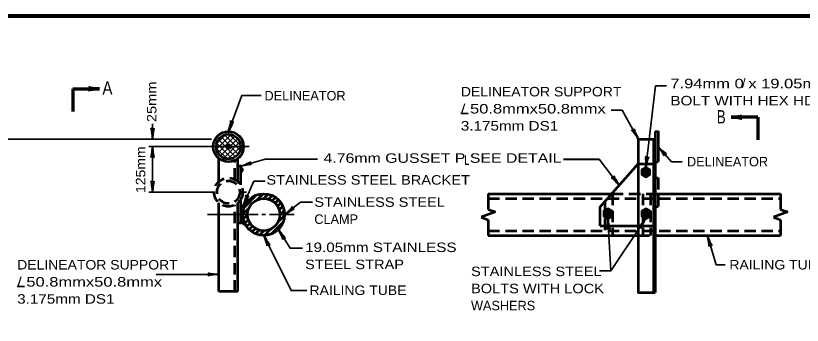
# Model space of a CAD drawing. Extents: x -105 to 751, y -65 to 479.
# Drawn here: x 59.6 to 308.2, y 374.9 to 472.7 of the extents above; entities that cross this region are included whole.
import ezdxf

# ---------------------------------------------------------------- set-up
doc = ezdxf.new("R2010")
doc.units = 0
doc.header["$LTSCALE"] = 1.2
doc.linetypes.add('MEDIUM_DASHED', pattern=[4.5, 3, -1.5])
doc.layers.add('1', color=7, linetype='Continuous', lineweight=35)

msp = doc.modelspace()

# ---------------------------------------------------------------- hatches: boundary and pattern name
at = {"layer": '1'}
msp.add_hatch(color=256, dxfattribs=at).paths.add_polyline_path([(127.405, 431.334, 1), (126.205, 431.334, 1)])

# ---------------------------------------------------------------- linework, layer by layer
at = {"layer": '1', "lineweight": 70}
for p, q in [((77.611, 449.646), (86.011, 449.646)), ((77.611, 449.646), (77.611, 442.446)), ((294.147, 440.646), (285.747, 440.646)), ((294.147, 440.646), (294.147, 433.446))]:
    msp.add_line(p, q, dxfattribs=at)
at = {"layer": '1'}
for p, q in [((200.312, 441.826), (202.577, 441.826)), ((102.805, 433.734), (102.805, 438.534)), ((130.681, 431.634), (127.105, 435.211)), ((-18.611, 433.734), (121.448, 433.734)), ((123.003, 430.516), (127.623, 435.136)), ((123.022, 432.232), (125.907, 435.117)), ((123.489, 429.305), (128.834, 434.65)), ((129.066, 428.158), (123.63, 433.594)), ((124.268, 428.387), (129.751, 433.871)), ((129.924, 428.997), (124.469, 434.452)), ((125.319, 427.741), (130.398, 432.82)), ((130.508, 430.111), (125.583, 435.036)), ((101.605, 431.334), (133.405, 431.334)), ((102.805, 416.934), (102.805, 431.334)), ((126.36, 427.47), (122.939, 430.891)), ((127.924, 427.603), (123.075, 432.452)), ((126.715, 427.44), (130.698, 431.423)), ((129.459, 428.487), (129.635, 428.663)), ((250.347, 419.101), (244.043, 427.366)), ((122.305, 416.934), (101.605, 416.934)), ((132.505, 416.934), (131.305, 416.934)), ((136.164, 409.868), (120.179, 409.868)), ((138.564, 409.868), (137.364, 409.868)), ((147.564, 409.868), (139.764, 409.868)), ((123.779, 390.962), (103.979, 390.962)), ((247.703, 392.118), (244.157, 392.118)), ((60.043, 387.126), (62.308, 387.126))]:
    msp.add_line(p, q, dxfattribs=at)
at = {"layer": '1', "lineweight": 53}
for p, q in [((261.747, 436.134), (261.747, 385.268)), ((256.347, 433.734), (261.747, 433.734)), ((261.147, 433.734), (261.147, 385.268)), ((123.779, 420.265), (123.779, 427.608)), ((129.779, 420.311), (129.779, 427.567)), ((256.347, 425.934), (261.147, 425.934)), ((261.747, 426.534), (262.647, 426.534)), ((130.679, 425.167), (129.779, 425.167)), ((130.679, 419.224), (130.679, 425.167)), ((130.679, 424.567), (130.679, 423.367)), ((257.448, 423.325), (258.817, 424.694)), ((257.448, 423.112), (258.952, 424.616)), ((257.448, 423.537), (258.507, 424.596)), ((257.448, 422.9), (259.086, 424.538)), ((257.448, 422.688), (259.22, 424.461)), ((257.448, 423.749), (258.005, 424.306)), ((257.448, 423.961), (257.503, 424.016)), ((257.453, 422.481), (258.31, 423.338)), ((257.588, 422.404), (258.311, 423.127)), ((257.722, 422.326), (258.376, 422.98)), ((257.857, 422.248), (258.48, 422.872)), ((257.991, 422.171), (258.623, 422.802)), ((258.125, 422.093), (258.824, 422.791)), ((258.26, 422.015), (260.046, 423.801)), ((258.394, 421.938), (260.046, 423.589)), ((258.529, 421.86), (260.046, 423.377)), ((258.644, 423.672), (259.355, 424.383)), ((258.663, 421.782), (260.046, 423.165)), ((258.854, 423.67), (259.489, 424.305)), ((258.937, 421.844), (260.046, 422.953)), ((259.001, 423.605), (259.624, 424.228)), ((259.109, 423.501), (259.758, 424.15)), ((259.178, 423.358), (259.893, 424.073)), ((259.189, 423.156), (260.027, 423.995)), ((259.439, 422.134), (260.046, 422.74)), ((259.941, 422.424), (260.046, 422.528)), ((131.764, 412.112), (135.725, 416.072)), ((135.843, 414.494), (137.808, 416.458)), ((138.004, 414.957), (139.357, 416.31)), ((139.474, 414.73), (140.635, 415.891)), ((140.638, 414.198), (141.729, 415.288)), ((208.947, 416.468), (208.947, 411.51)), ((208.947, 416.468), (248.035, 416.468)), ((261.747, 416.468), (301.347, 416.468)), ((301.347, 416.468), (301.347, 411.51)), ((123.779, 385.562), (123.779, 413.603)), ((129.779, 385.562), (129.779, 413.557)), ((130.679, 407.162), (130.679, 414.645)), ((130.679, 412.262), (132.248, 413.168)), ((141.584, 413.446), (142.644, 414.506)), ((142.332, 412.497), (143.418, 413.583)), ((130.679, 409.262), (130.679, 410.462)), ((130.679, 410.462), (130.679, 409.262)), ((131.372, 410.023), (133.333, 411.983)), ((142.85, 411.317), (144.013, 412.481)), ((143.062, 409.833), (144.42, 411.191)), ((211.202, 410.689), (206.692, 409.048)), ((208.947, 411.51), (211.202, 410.689)), ((245.482, 410.326), (246.808, 411.653)), ((245.482, 410.114), (246.943, 411.575)), ((245.482, 409.902), (247.077, 411.497)), ((245.482, 410.538), (246.381, 411.438)), ((245.482, 409.69), (247.212, 411.42)), ((245.482, 410.751), (245.879, 411.148)), ((245.482, 409.478), (246.386, 410.382)), ((246.251, 408.974), (248.08, 410.803)), ((246.386, 408.897), (248.08, 410.591)), ((246.52, 408.819), (248.08, 410.379)), ((246.567, 410.563), (247.346, 411.342)), ((246.831, 410.615), (247.481, 411.264)), ((246.992, 410.564), (247.615, 411.187)), ((247.112, 410.471), (247.75, 411.109)), ((247.195, 410.342), (247.884, 411.031)), ((247.231, 410.166), (248.019, 410.954)), ((257.507, 410.275), (258.865, 411.634)), ((257.507, 410.063), (259, 411.556)), ((257.507, 410.488), (258.526, 411.507)), ((257.507, 409.851), (259.134, 411.479)), ((257.507, 409.639), (259.269, 411.401)), ((257.507, 410.7), (258.024, 411.217)), ((257.507, 410.912), (257.522, 410.927)), ((257.507, 409.427), (258.376, 410.296)), ((258.308, 408.956), (260.105, 410.752)), ((258.443, 408.878), (260.105, 410.54)), ((258.577, 408.8), (260.105, 410.328)), ((258.678, 410.599), (259.403, 411.323)), ((258.899, 410.607), (259.538, 411.246)), ((259.05, 410.546), (259.672, 411.168)), ((259.161, 410.445), (259.807, 411.091)), ((259.234, 410.305), (259.941, 411.013)), ((259.251, 410.11), (260.076, 410.935)), ((303.602, 410.689), (299.091, 409.048)), ((301.347, 411.51), (303.602, 410.689)), ((131.521, 408.474), (132.866, 409.82)), ((131.942, 407.198), (133.098, 408.355)), ((142.512, 407.586), (144.552, 409.626)), ((206.692, 409.048), (208.947, 408.227)), ((208.947, 408.227), (208.947, 403.268)), ((245.579, 409.363), (246.334, 410.118)), ((245.713, 409.285), (246.385, 409.957)), ((245.848, 409.207), (246.478, 409.837)), ((245.982, 409.13), (246.607, 409.755)), ((246.117, 409.052), (246.784, 409.719)), ((246.655, 408.741), (248.08, 410.167)), ((246.812, 408.686), (248.08, 409.954)), ((247.313, 408.976), (248.08, 409.742)), ((247.815, 409.266), (248.08, 409.53)), ((257.636, 409.344), (258.367, 410.075)), ((257.77, 409.266), (258.429, 409.925)), ((257.905, 409.189), (258.53, 409.814)), ((258.039, 409.111), (258.668, 409.74)), ((258.174, 409.033), (258.864, 409.724)), ((258.712, 408.723), (260.105, 410.116)), ((258.957, 408.756), (260.105, 409.904)), ((259.459, 409.045), (260.105, 409.692)), ((259.961, 409.335), (260.105, 409.479)), ((299.091, 409.048), (301.347, 408.227)), ((301.347, 408.227), (301.347, 403.268)), ((130.679, 407.162), (129.779, 407.162)), ((130.679, 407.462), (132.26, 406.549)), ((132.546, 406.105), (133.629, 407.188)), ((133.327, 405.189), (134.387, 406.249)), ((134.252, 404.417), (135.342, 405.507)), ((138.21, 403.284), (140.242, 405.316)), ((140.339, 403.716), (144.122, 407.499)), ((244.347, 406.268), (261.147, 406.268)), ((135.351, 403.819), (136.519, 404.987)), ((136.643, 403.414), (138.009, 404.78)), ((208.947, 403.268), (256.347, 403.268)), ((261.747, 403.268), (301.347, 403.268)), ((129.779, 385.562), (123.779, 385.562))]:
    msp.add_line(p, q, dxfattribs=at)
at = {"layer": '1', "linetype": 'MEDIUM_DASHED', "lineweight": 53}
for p, q in [((128.879, 420.928), (128.879, 427.005)), ((261.747, 421.434), (262.647, 421.434)), ((262.647, 421.434), (262.647, 412.434)), ((248.035, 416.468), (261.147, 416.468)), ((248.247, 416.468), (248.247, 403.268)), ((257.847, 416.468), (257.847, 403.268)), ((128.879, 385.562), (128.879, 412.941)), ((208.947, 414.968), (301.347, 414.968)), ((245.847, 413.977), (245.847, 403.268)), ((261.747, 412.434), (262.647, 412.434)), ((208.947, 404.768), (301.347, 404.768)), ((256.347, 403.268), (261.747, 403.268))]:
    msp.add_line(p, q, dxfattribs=at)
at = {"layer": '1', "lineweight": 40}
msp.add_line((232.729, 427.366), (244.043, 427.366), dxfattribs=at)
at = {"layer": '1', "lineweight": 158}
msp.add_lwpolyline([(744.128, 472.7), (-47.572, 472.6), (-47.472, -53.4)], dxfattribs=at)
at = {"layer": '1'}
for points in [[(258.747, 424.734), (261.831, 450.506), (265.252, 450.506)], [(126.805, 436.134), (131.091, 447.514), (137.193, 447.514)], [(256.347, 433.734), (251.249, 442.823), (247.807, 442.823)], [(262.647, 431.334), (266.894, 426.547), (270.232, 426.547)], [(130.679, 425.167), (138.369, 427.366), (154.96, 427.366)], [(131.464, 412.715), (134.84, 420.381), (138.369, 420.381)], [(144.564, 409.868), (149.615, 413.763), (153.364, 413.763)], [(246.781, 408.668), (247.703, 392.118), (258.806, 408.668)], [(137.964, 403.268), (146.619, 385.826), (151.617, 385.826)], [(142.631, 405.202), (146.308, 399.277), (150.204, 399.277)], [(278.236, 403.268), (280.974, 393.995), (283.895, 393.995)]]:
    msp.add_lwpolyline(points, dxfattribs=at)
at = {"layer": '1', "lineweight": 53}
for points in [[(261.747, 436.134), (262.647, 436.134), (262.647, 426.534)], [(256.347, 433.734), (256.347, 385.268), (261.747, 385.268)], [(244.347, 406.268), (244.347, 412.268), (256.347, 425.934)]]:
    msp.add_lwpolyline(points, dxfattribs=at)
for points in [[(258.747, 421.734), (260.046, 422.484), (260.046, 423.984), (258.747, 424.734), (257.448, 423.984), (257.448, 422.484)], [(246.781, 408.668), (248.08, 409.418), (248.08, 410.918), (246.781, 411.668), (245.482, 410.918), (245.482, 409.418)], [(258.806, 408.668), (260.105, 409.418), (260.105, 410.918), (258.806, 411.668), (257.507, 410.918), (257.507, 409.418)]]:
    msp.add_lwpolyline(points, close=True, dxfattribs=at)
at = {"layer": '1', "linetype": 'MEDIUM_DASHED', "lineweight": 53}
msp.add_lwpolyline([(260.247, 416.468), (260.247, 416.427), (260.247, 403.268)], dxfattribs=at)
at = {"layer": '1', "lineweight": 53}
for centre, radius in [((126.805, 431.334), 4.8), ((126.805, 431.334), 3.9), ((126.805, 431.334), 0.6), ((258.747, 423.234), 0.45), ((137.964, 409.868), 6.6), ((137.964, 409.868), 5.1), ((246.781, 410.168), 0.45), ((258.806, 410.168), 0.45)]:
    msp.add_circle(centre, radius, dxfattribs=at)
at = {"layer": '1', "linetype": 'MEDIUM_DASHED', "lineweight": 53}
for radius in [4.5, 3.6]:
    msp.add_circle((126.805, 416.934), radius, dxfattribs=at)
at = {"layer": '1', "lineweight": 53}
for centre in [(130.659, 423.967), (130.659, 409.862)]:
    msp.add_arc(centre, 0.6, 271.87043, 88.12958, dxfattribs=at)
at = {"layer": '1', "lineweight": 70}
for centre, major_axis, ratio, start_param, end_param in [((84.709, 449.974), (2.145, -0.165), 0.122415, 3.1415927, 5.386832), ((84.68, 449.388), (2.105, 0.233), 0.07063, 0.8650754, 3.1424706), ((287.078, 440.388), (-2.105, 0.233), 0.07063, 3.1407148, 5.41811), ((287.049, 440.974), (-2.145, -0.165), 0.122415, 0.8963533, 3.1415927)]:
    msp.add_ellipse(centre, major_axis=major_axis, ratio=ratio, start_param=start_param, end_param=end_param, dxfattribs=at)
at = {"layer": '1', "lineweight": 40}
for centre, major_axis, ratio, start_param, end_param in [((126.956, 437.476), (-0.58, -2.071), 0.122415, 0.8963533, 3.1415927), ((126.956, 437.476), (-0.58, -2.071), 0.122415, 0.8963533, 3.1415927), ((127.516, 437.303), (0.94, 1.898), 0.07063, 6.2823074, 8.5597026), ((127.516, 437.303), (0.94, 1.898), 0.07063, 6.2823074, 8.5597026), ((102.473, 435.044), (0.187, -2.143), 0.122415, 0.8963533, 3.1415927), ((102.473, 435.044), (0.187, -2.143), 0.122415, 0.8963533, 3.1415927), ((103.059, 435.079), (-0.211, -2.108), 0.07063, 3.1407148, 5.41811), ((103.059, 435.079), (-0.211, -2.108), 0.07063, 3.1407148, 5.41811), ((255.417, 434.714), (1.212, -1.777), 0.122415, 0.8963533, 3.1415927), ((255.417, 434.714), (1.212, -1.777), 0.122415, 0.8963533, 3.1415927), ((255.911, 435.031), (0.847, -1.941), 0.07063, 3.1407148, 5.41811), ((255.911, 435.031), (0.847, -1.941), 0.07063, 3.1407148, 5.41811), ((102.551, 429.99), (0.211, 2.108), 0.07063, 3.1407148, 5.41811), ((102.551, 429.99), (0.211, 2.108), 0.07063, 3.1407148, 5.41811), ((103.136, 430.025), (-0.187, 2.143), 0.122415, 0.8963533, 3.1415927), ((103.136, 430.025), (-0.187, 2.143), 0.122415, 0.8963533, 3.1415927), ((263.349, 430.16), (-1.241, 1.717), 0.07063, 3.1407148, 5.41811), ((263.764, 430.575), (-1.562, 1.479), 0.122415, 0.8963533, 3.1415927), ((258.573, 426.074), (-0.069, -2.15), 0.122415, 0.8963533, 3.1415927), ((258.573, 426.074), (-0.069, -2.15), 0.122415, 0.8963533, 3.1415927), ((259.159, 426.039), (-0.46, -2.068), 0.07063, 3.1407148, 5.41811), ((259.159, 426.039), (-0.46, -2.068), 0.07063, 3.1407148, 5.41811), ((131.847, 425.845), (-2.009, -0.769), 0.122415, 0.8963533, 3.1415927), ((131.847, 425.845), (-2.009, -0.769), 0.122415, 0.8963533, 3.1415927), ((132.041, 425.292), (-2.084, -0.377), 0.07063, 3.1407148, 5.41811), ((132.041, 425.292), (-2.084, -0.377), 0.07063, 3.1407148, 5.41811), ((102.473, 418.244), (0.187, -2.143), 0.122415, 0.8963533, 3.1415927), ((102.473, 418.244), (0.187, -2.143), 0.122415, 0.8963533, 3.1415927), ((103.059, 418.279), (-0.211, -2.108), 0.07063, 3.1407148, 5.41811), ((103.059, 418.279), (-0.211, -2.108), 0.07063, 3.1407148, 5.41811), ((249.289, 419.941), (1.449, -1.59), 0.122415, 0.8963533, 3.1415927), ((249.289, 419.941), (1.449, -1.59), 0.122415, 0.8963533, 3.1415927), ((249.733, 420.324), (1.111, -1.804), 0.07063, 3.1407148, 5.41811), ((249.733, 420.324), (1.111, -1.804), 0.07063, 3.1407148, 5.41811), ((131.688, 414.047), (-0.692, -2.037), 0.122415, 0.8963533, 3.1415927), ((132.238, 413.843), (-1.043, -1.844), 0.07063, 3.1407148, 5.41811), ((145.399, 410.931), (-1.583, -1.457), 0.122415, 0.8963533, 3.1415927), ((145.399, 410.931), (-1.583, -1.457), 0.122415, 0.8963533, 3.1415927), ((145.784, 410.488), (1.798, 1.12), 0.07063, 6.2823074, 8.5597026), ((145.784, 410.488), (1.798, 1.12), 0.07063, 6.2823074, 8.5597026), ((246.602, 407.312), (0.093, 2.116), 0.07063, 3.1407148, 5.41811), ((247.185, 407.379), (-0.306, 2.129), 0.122415, 0.8963533, 3.1415927), ((257.846, 407.693), (-1.349, -1.633), 0.07063, 6.2823074, 8.5597026), ((258.352, 407.396), (1.038, 1.884), 0.122415, 0.8963533, 3.1415927), ((138.334, 401.951), (0.748, -1.982), 0.07063, 6.2823074, 8.5597026), ((138.843, 402.243), (-1.12, 1.836), 0.122415, 0.8963533, 3.1415927), ((143.124, 403.925), (0.932, -1.902), 0.07063, 6.2823074, 8.5597026), ((143.124, 403.925), (0.932, -1.902), 0.07063, 6.2823074, 8.5597026), ((143.603, 404.264), (-1.289, 1.722), 0.122415, 0.8963533, 3.1415927), ((143.603, 404.264), (-1.289, 1.722), 0.122415, 0.8963533, 3.1415927), ((278.373, 401.907), (-0.395, 2.081), 0.07063, 3.1407148, 5.41811), ((278.373, 401.907), (-0.395, 2.081), 0.07063, 3.1407148, 5.41811), ((278.924, 402.107), (-0.787, 2.002), 0.122415, 0.8963533, 3.1415927), ((278.924, 402.107), (-0.787, 2.002), 0.122415, 0.8963533, 3.1415927), ((122.469, 390.63), (2.143, 0.187), 0.122415, 0.8963533, 3.1415927), ((122.434, 391.216), (2.108, -0.211), 0.07063, 3.1407148, 5.41811)]:
    msp.add_ellipse(centre, major_axis=major_axis, ratio=ratio, start_param=start_param, end_param=end_param, dxfattribs=at)

# ---------------------------------------------------------------- texts
at = {"layer": '1'}
for s, height, width, p in [('7.94mm 0 x 19.05mm LG. STAINLESS STEEL', 3, 1.3, (266.524, 449.773)), ('A', 4.2, 0.85, (86.958, 447.765)), ('DELINEATOR SUPPORT', 3, 1.1, (200.288, 447.207)), ('BOLT WITH HEX HD. LOCK NUT', 3, 1.2, (266.524, 444.373)), ('/ 50.8mmx50.8mmx', 3, 1.3, (200.288, 441.807)), ('B', 4.2, 0.75, (281.189, 438.663)), ('3.175mm DS1', 3, 1.2, (200.288, 436.407)), ('4.76mm GUSSET P SEE DETAIL', 3, 1.25, (156.858, 426.221)), ('L', 3, 0.75, (201.331, 425.571)), ('STAINLESS STEEL BRACKET', 3, 1.15, (138.809, 419.325)), ('STAINLESS STEEL', 3, 1.15, (153.961, 412.319)), ('19.05mm STAINLESS', 3, 1.2, (151.039, 398.028)), ('DELINEATOR SUPPORT', 3, 1.1, (60.019, 392.507)), ('STEEL STRAP', 3, 1.15, (151.039, 392.628)), ('RAILING TUBE', 3, 1.1, (285.173, 392.519)), ('STAINLESS STEEL', 3, 1.15, (203.498, 390.414)), ('/ 50.8mmx50.8mmx', 3, 1.3, (60.019, 387.107)), ('BOLTS WITH LOCK', 3, 1.15, (203.498, 385.014)), ('RAILING TUBE', 3, 1.1, (152.446, 384.464)), ('3.175mm DS1', 3, 1.2, (60.019, 381.707))]:
    msp.add_text(s, height=height, dxfattribs=dict(at, width=width)).set_placement(p)
for s, p in [('/', (289.162, 449.87)), ('DELINEATOR', (138.212, 445.93)), ('DELINEATOR', (271.773, 425.098)), ('CLAMP', (153.961, 406.919)), ('WASHERS', (203.498, 379.614))]:
    msp.add_text(s, height=3, dxfattribs=at).set_placement(p)
for s, width, p in [('25mm', 1.15, (104.047, 439.094)), ('125mm', 1.1, (100.54, 416.694))]:
    msp.add_text(s, height=3, rotation=90, dxfattribs=dict(at, width=width)).set_placement(p)

doc.saveas('drawing.dxf')
